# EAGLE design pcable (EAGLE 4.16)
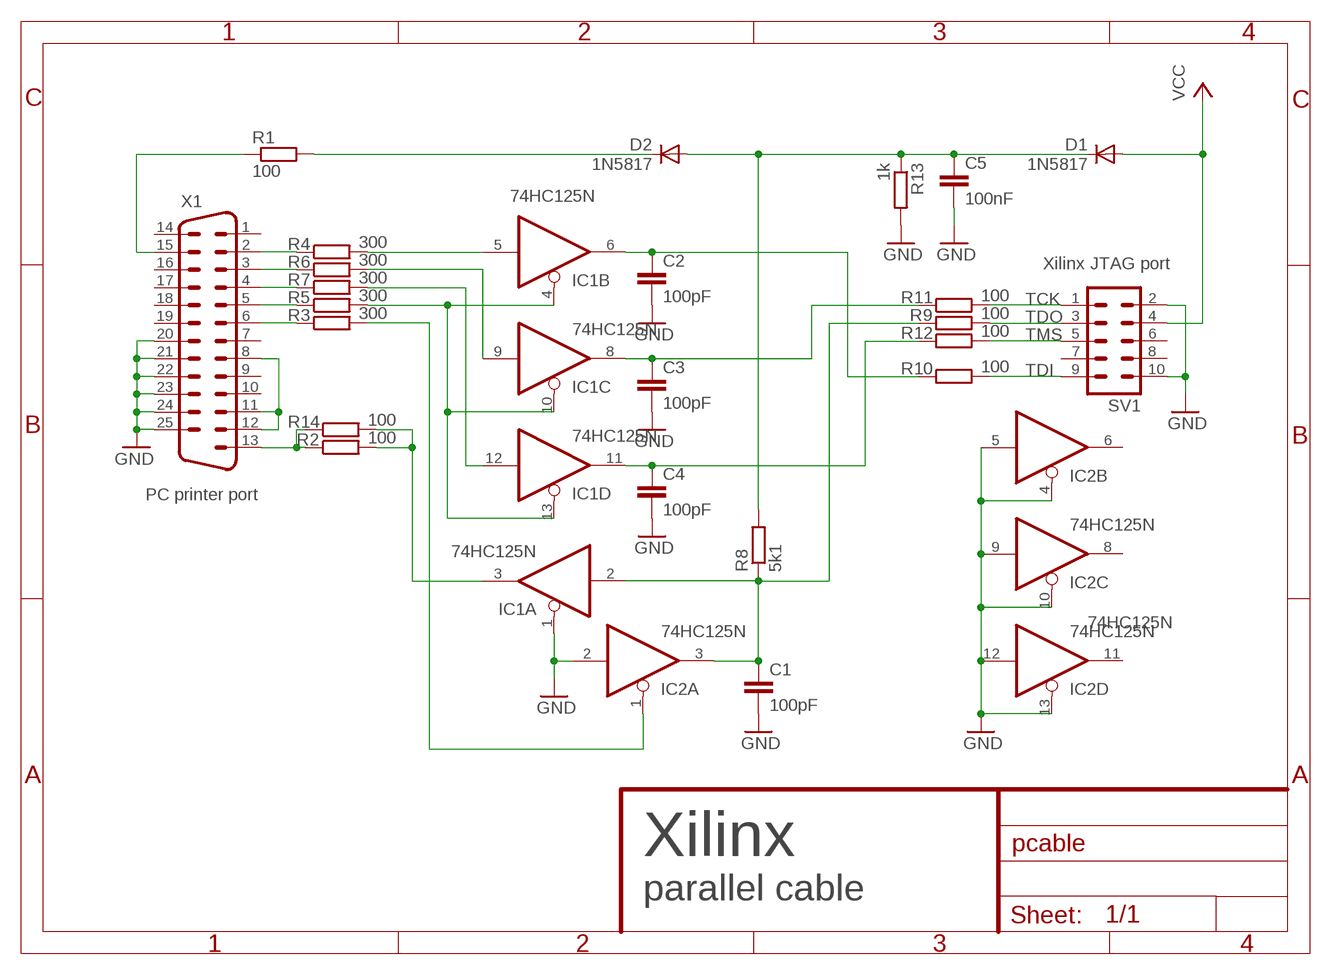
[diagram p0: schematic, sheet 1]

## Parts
C1  100pF  C-EU025-025X050  [C025-025X050]
C2  100pF  C-EU025-025X050  [C025-025X050]
C3  100pF  C-EU025-025X050  [C025-025X050]
C4  100pF  C-EU025-025X050  [C025-025X050]
C5  100nF  C-EU050-025X075  [C050-025X075]
D1  1N5817  1N4933  [DO41-10]
D2  1N5817  1N4933  [DO41-10]
IC1  74HC125N  [DIL14]
IC2  74HC125N  [DIL14]
R1  100  R-EU_0204/2V  [0204V]
R2  100  R-EU_0204/2V  [0204V]
R3  300  R-EU_0204/2V  [0204V]
R4  300  R-EU_0204/2V  [0204V]
R5  300  R-EU_0204/2V  [0204V]
R6  300  R-EU_0204/2V  [0204V]
R7  300  R-EU_0204/2V  [0204V]
R8  5k1  R-EU_0204/2V  [0204V]
R9  100  R-EU_0204/2V  [0204V]
R10  100  R-EU_0204/2V  [0204V]
R11  100  R-EU_0204/2V  [0204V]
R12  100  R-EU_0204/2V  [0204V]
R13  1k  R-EU_0204/2V  [0204V]
R14  100  R-EU_0204/2V  [0204V]
SV1  ML10  [ML10]
X1  M25D  [M25D]

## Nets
GND: C1.2 C2.2 C3.2 C4.2 C5.2 IC1.1(A:OE) IC2.2(A:I) IC2.4(B:OE) IC2.5(B:I) IC2.9(C:I) IC2.10(C:OE) IC2.12(D:I) IC2.13(D:OE) R13.2 SV1.2 SV1.10 X1.20 X1.21 X1.22 X1.23 X1.24 X1.25
N$1: X1.8 X1.11 X1.12
N$2: R1.1 X1.15
N$3: R3.1 X1.6
N$4: R4.1 X1.2
N$5: R5.1 X1.5
N$6: R7.1 X1.4
N$7: R6.1 X1.3
N$8: IC1.5(B:I) R4.2
N$9: IC1.4(B:OE) IC1.10(C:OE) IC1.13(D:OE) R5.2
N$10: R2.1 R14.1 X1.13
N$11: IC1.9(C:I) R6.2
N$12: IC1.12(D:I) R7.2
N$13: IC2.1(A:OE) R3.2
N$14: IC1.3(A:O) R2.2 R14.2
N$15: D2.C R1.2
N$16: C5.1 D1.C D2.A R8.2 R13.1
N$17: C1.1 IC1.2(A:I) IC2.3(A:O) R8.1 R9.1
N$18: C4.1 IC1.11(D:O) R12.1
N$19: C3.1 IC1.8(C:O) R11.1
N$20: C2.1 IC1.6(B:O) R10.1
TCK: R11.2 SV1.1
TDI: R10.2 SV1.9
TDO: R9.2 SV1.3
TMS: R12.2 SV1.5
VCC: D1.A SV1.4
Unconnected: IC2.6(B:O) IC2.8(C:O) IC2.11(D:O) SV1.6 SV1.7 SV1.8 X1.1 X1.7 X1.9 X1.10 X1.14 X1.16 X1.17 X1.18 X1.19

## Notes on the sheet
- Xilinx JTAG port
- PC printer port
- Xilinx
- parallel cable

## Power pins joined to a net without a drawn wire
GND: IC1.7(P:GND) IC2.7(P:GND)
VCC: IC1.14(P:VCC) IC2.14(P:VCC)

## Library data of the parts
C1-C5 = rcl:C-EU: CAPACITOR, European symbol
D1 D2 = diode:1N4933: DIODE
IC1 IC2 = 74xx-eu:74*125: Quad bus BUFFER, 3-state
R1-R14 = rcl:R-EU_: RESISTOR, European symbol
SV1 = con-harting-ml:ML10: HARTING
X1 = con-subd:M25: SUB-D

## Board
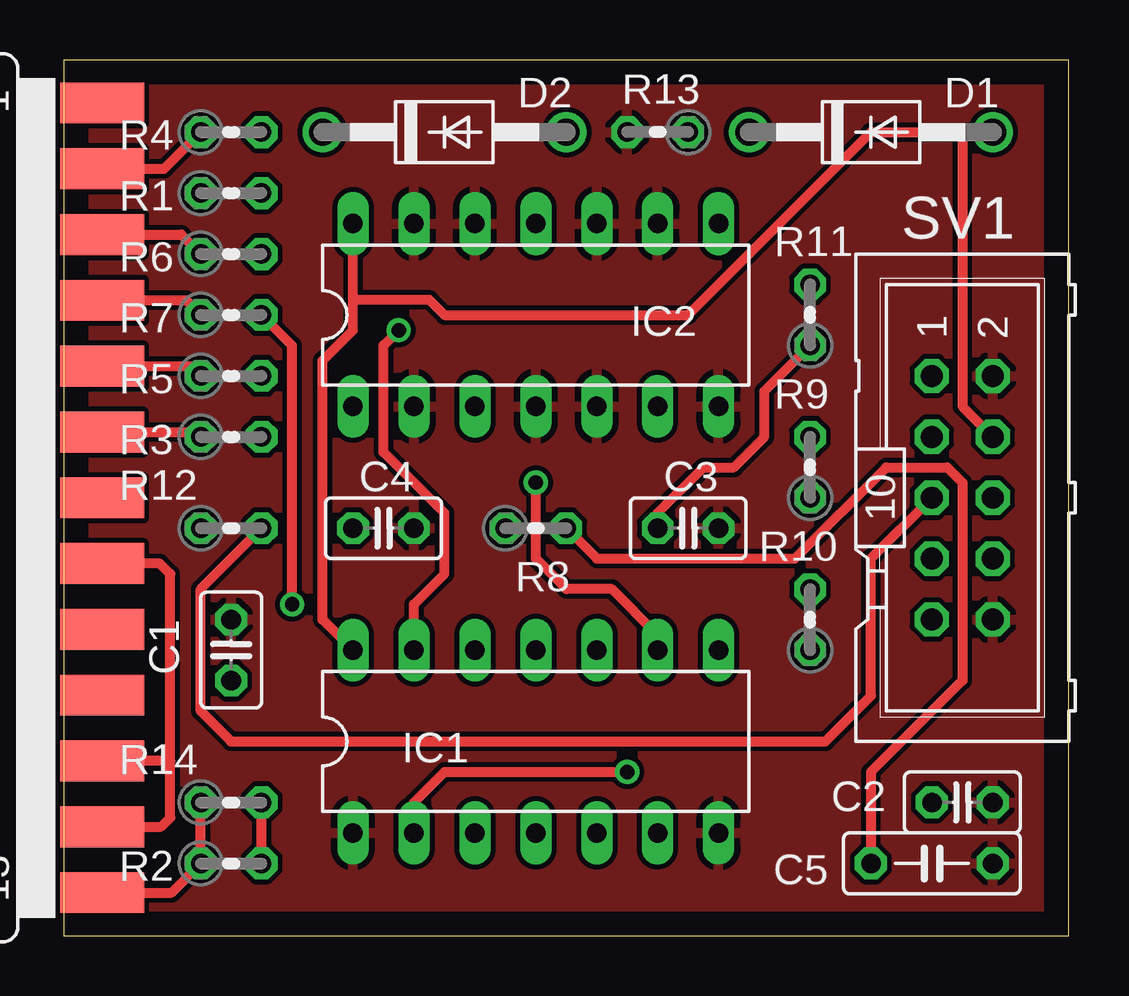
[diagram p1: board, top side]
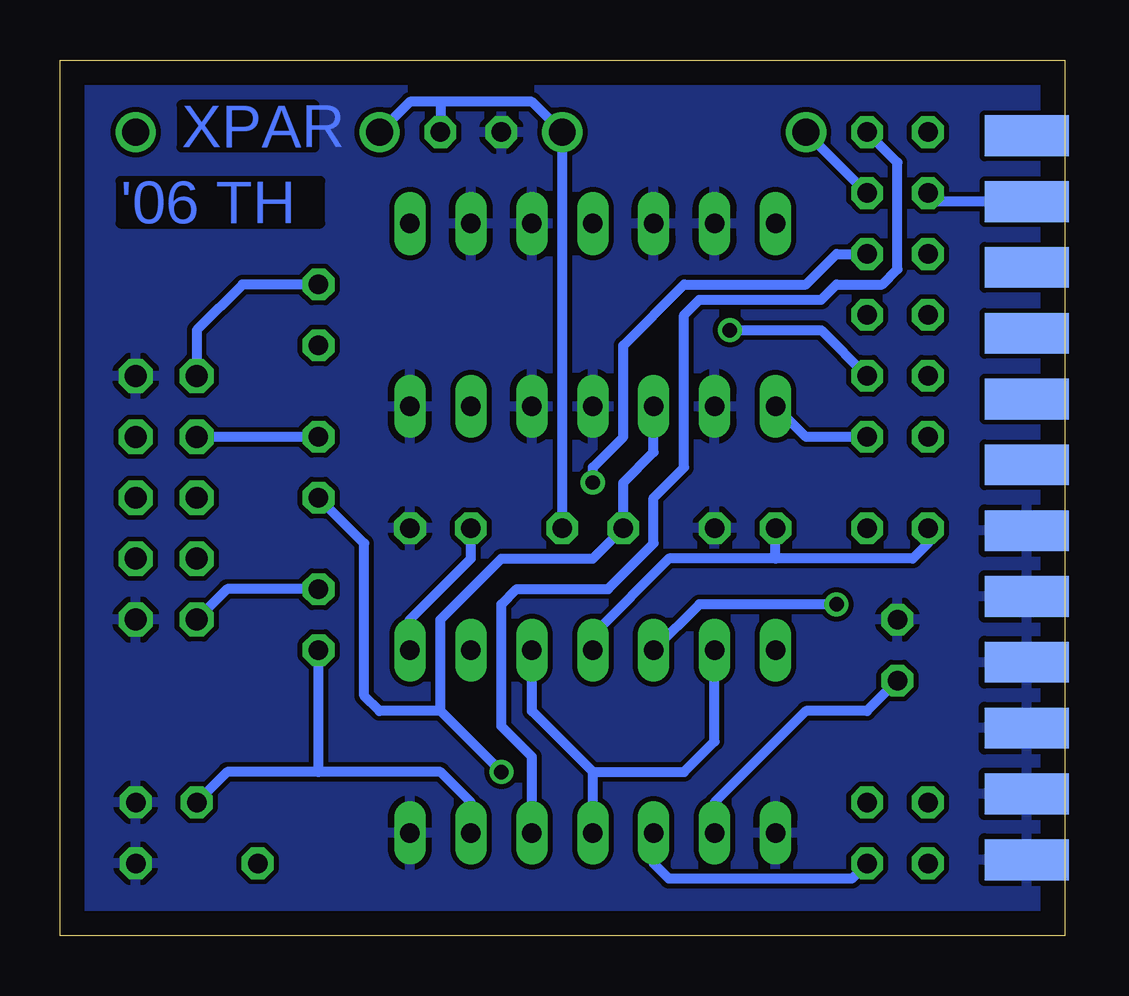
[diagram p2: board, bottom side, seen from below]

Size 41.89 x 36.5 mm. Coordinates in mm from the lower left corner, seen from the top.
Outline: 0,0 41.89,0 41.89,36.5 0,36.5 0,0
Copper layers (1*16): Top 0.035mm / dielectric 1.5mm / Bottom 0.035mm
Design rules "default": minimum track width 10mil, minimum drill 24mil, track to track 8mil, track to pad 8mil, pad to pad 8mil, via to via 8mil, smd to smd 8mil, copper to edge 40mil, drill to drill 8mil, minimum pad ring 10mil, minimum via ring 8mil, stop-mask expansion 4mil, vias tented up to drill 0mil, thermal gap 10mil

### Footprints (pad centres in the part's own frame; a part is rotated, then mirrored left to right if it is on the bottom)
C025-025X050 = drill 0.813 octagon: 1 -1.27,0; 2 1.27,0
C050-025X075 = drill 0.813 octagon: 1 -2.54,0; 2 2.54,0
DO41-10 = drill 1.118 round: A 5.08,0; C -5.08,0
DIL14 = drill 0.813 long: 1 -7.62,-3.81; 2 -5.08,-3.81; 3 -2.54,-3.81; 4 0,-3.81; 5 2.54,-3.81; 6 5.08,-3.81; 7 7.62,-3.81; 8 7.62,3.81; 9 5.08,3.81; 10 2.54,3.81; 11 0,3.81; 12 -2.54,3.81; 13 -5.08,3.81; 14 -7.62,3.81
0204V = drill 0.813 octagon: 1 -1.27,0; 2 1.27,0
ML10 = drill 0.914 octagon: 1 -5.08,-1.27; 2 -5.08,1.27; 3 -2.54,-1.27; 4 -2.54,1.27; 5 0,-1.27; 6 0,1.27; 7 2.54,-1.27; 8 2.54,1.27; 9 5.08,-1.27; 10 5.08,1.27
M25D = smd 1.7 x 3.5: 1 16.459,-6.045; 2 13.716,-6.045; 3 10.973,-6.045; 4 8.23,-6.045; 5 5.486,-6.045; 6 2.743,-6.045; 7 0,-6.045; 8 -2.743,-6.045; 9 -5.486,-6.045; 10 -8.23,-6.045; 11 -10.973,-6.045; 12 -13.716,-6.045; 13 -16.459,-6.045 | smd 1.7 x 3.5 bottom: 14 15.088,-6.045; 15 12.344,-6.045; 16 9.601,-6.045; 17 6.858,-6.045; 18 4.115,-6.045; 19 1.372,-6.045; 20 -1.372,-6.045; 21 -4.115,-6.045; 22 -6.858,-6.045; 23 -9.601,-6.045; 24 -12.344,-6.045; 25 -15.088,-6.045

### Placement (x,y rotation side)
C1  6.98,11.9 90 top
C2  37.46,5.55 0 top
C3  26.03,16.98 0 top
C4  13.33,16.98 0 top
C5  36.19,3.01 0 top
D1  33.65,33.49 0 top
D2  15.87,33.49 0 top
IC1  19.68,8.09 0 top
IC2  19.68,25.87 0 top
R1  6.98,30.95 0 top
R2  6.98,3.01 0 top
R3  6.98,20.79 0 top
R4  6.98,33.49 0 top
R5  6.98,23.33 0 top
R6  6.98,28.41 0 top
R7  6.98,25.87 0 top
R8  19.68,16.98 0 top
R9  31.11,19.52 90 top
R10  31.11,13.17 90 top
R11  31.11,25.87 90 top
R12  6.98,16.98 0 top
R13  24.76,33.49 180 top
R14  6.98,5.55 0 top
SV1  37.46,18.25 270 top
X1  -4.45,18.25 90 top

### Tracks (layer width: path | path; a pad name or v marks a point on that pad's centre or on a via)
GND
  pour Bottom: -0.01,-0.17 -0.01,36.66 41.91,36.66 41.91,-0.17
  pour Top: -0.01,-0.17 -0.01,36.66 41.91,36.66 41.91,-0.17
N$1
  Top 0.406: 4.44,7.28 X1.11 | X1.12 4.06,4.53 4.44,4.92 4.44,7.28 | X1.8 4.01,15.51 4.44,15.08 4.44,7.28
N$2
  Bottom 0.406: X1.15 5.35,30.59 R1.1
N$3
  Top 0.406: X1.6 5.51,20.99 R3.1
N$4
  Top 0.406: X1.2 4.19,31.97 R4.1
N$5
  Top 0.406: X1.5 5.3,23.74 R5.1
N$6
  Top 0.406: X1.4 5.1,26.48 R7.1
N$7
  Top 0.406: X1.3 4.9,29.22 R6.1
N$8
  Bottom 0.406: IC1.5 22.22,7.46 23.49,8.73 23.49,13.81 22.86,14.44 19.04,14.44 17.14,16.34 17.14,18.25 15.87,19.52 15.87,25.87 15.24,26.5 10.16,26.5 9.52,27.14 7.62,27.14 6.98,27.77 6.98,32.22 R4.2
N$9  (via drill 0.6)
  Top 0.406: IC1.13 14.6,13.81 15.87,15.08 15.87,17.61 13.33,20.15 13.33,24.6 v13.97,25.23
  Bottom 0.406: IC1.4 19.68,6.82 | 19.68,6.82 22.22,9.36 IC1.10 | IC1.13 14.6,8.09 15.87,6.82 19.68,6.82 | v13.97,25.23 10.16,25.23 R5.2
N$10
  Top 0.406: X1.13 4.49,1.79 R2.1 R14.1
N$11  (via drill 0.6)
  Top 0.406: IC1.9 24.76,12.54 22.86,14.44 20.95,14.44 19.68,15.71 v19.68,18.88
  Bottom 0.406: v19.68,18.88 19.68,19.52 18.41,20.79 18.41,24.6 15.87,27.14 10.79,27.14 9.52,28.41 R6.2
N$12  (via drill 0.6)
  Top 0.406: R7.2 9.52,24.6 v9.52,13.81
  Bottom 0.406: v9.52,13.81 15.24,13.81 IC1.12
N$13
  Bottom 0.406: R3.2 10.79,20.79 IC2.1
N$14
  Top 0.406: R2.2 R14.2
  Bottom 0.406: IC1.3 17.14,3.01 16.5,2.38 8.89,2.38 R2.2
N$15
  Bottom 0.406: R1.2 D2.C
N$16
  Top 0.406: R8.2 22.22,15.71 30.47,15.71 34.29,19.52 36.83,19.52 37.46,18.88 37.46,10.63 33.65,6.82 C5.1
  Bottom 0.406: 26.03,34.76 22.22,34.76 D2.A R8.2 | 26.03,34.76 27.3,34.76 D1.C | 26.03,34.76 R13.1
N$17  (via drill 0.6)
  Top 0.406: IC1.2 14.6,5.55 15.87,6.82 v23.49,6.82
  Bottom 0.406: IC1.2 14.6,5.55 10.79,9.36 8.25,9.36 C1.1 | IC2.3 17.14,20.15 18.41,18.88 R8.1 19.68,15.71 23.49,15.71 26.03,13.17 26.03,9.36 | 26.03,9.36 28.57,9.36 29.2,10 29.2,16.34 R9.1 | v23.49,6.82 26.03,9.36
N$18
  Bottom 0.406: IC1.11 19.68,12.54 16.5,15.71 12.06,15.71 | R12.1 5.71,16.34 6.34,15.71 12.06,15.71 | 12.06,15.71 C4.1
N$19
  Top 0.406: C3.1 24.76,17.61 26.66,19.52 27.93,19.52 29.2,20.79 29.2,22.7 R11.1
  Bottom 0.406: IC1.8 27.3,13.17 24.76,15.71 C3.1
N$20
  Bottom 0.406: IC1.6 24.76,5.55 26.03,6.82 | 26.03,6.82 31.11,6.82 R10.1 | C2.1 34.92,6.82 26.03,6.82
TCK
  Bottom 0.406: SV1.1 36.19,25.23 34.29,27.14 R11.2
TDI
  Bottom 0.406: R10.2 34.92,14.44 SV1.9
TDO
  Bottom 0.406: R9.2 SV1.3
TMS
  Top 0.406: R12.2 5.71,14.44 5.71,9.36 6.98,8.09 31.74,8.09 33.65,10 33.65,15.71 SV1.5
VCC
  Top 0.406: 12.06,26.5 12.06,25.23 10.79,23.96 10.79,13.17 IC1.14 | 12.06,26.5 IC2.14 | 37.46,33.49 33.65,33.49 26.03,25.87 15.87,25.87 15.24,26.5 12.06,26.5 | 37.46,33.49 D1.A | SV1.4 37.46,22.06 37.46,33.49

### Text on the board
Bottom: XPAR | '06 TH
